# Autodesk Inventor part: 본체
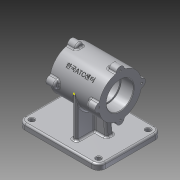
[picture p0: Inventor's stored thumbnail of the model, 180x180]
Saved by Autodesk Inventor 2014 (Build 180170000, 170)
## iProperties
Created: 2015-12
Part Number: 본체
Material: Aluminum 6061
Document SubType Name: Modeling
Designer: user
Density: 2.71 g/cm^3
Appearance: Aluminum - Flat
Author: user
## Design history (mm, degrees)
sketch "Sketch1"
  geometry: L1 (-42.5, 37)-(42.5, 37); L2 (42.5, 37)-(42.5, 0); L3 (42.5, 0)-(-42.5, 0); L4 (-42.5, 0)-(-42.5, 37); 2 further points
  constraints: 8 end point, 2 parallel, 1 coincident, 1 horizontal, 1 midpoint, 1 perpendicular
  dimensions: "d0" = 74 diameter of L1 L3; "d1" = 85 distance between parallel lines of L2 L4
revolve "Revolution1" sketch "Sketch1" stored, may be unused: angle "d2" = 90 deg
sketch "Sketch2"
  geometry: L1 (0, 1.084)-(0, 37); C1 r 7 at (0, 37); 2 further points
  constraints: 2 end point, 1 centre point, 1 coincident, 1 vertical, 1 vertical alignment, 1 other
  dimensions: "d3" = 14 diameter of C1
extrude "Extrusion1" join sketch "Sketch2" distance "d4" = 15; taper "d5" = 0 deg
mirror "Mirror1"
mirror "Mirror2"
sketch "Sketch5"
  geometry: L1 (-37, -37)-(37, -37); C1 r 7 at (-37, -37); A1 r 37 centre (0, -37) between (-6.969, -0.662) and (-6.969, -73.338) reference; A2 r 37 centre (0, -37) between (6.969, -73.338) and (6.969, -0.662) reference; 1 further point
  constraints: 2 end point, 2 point on circle, 1 centre point, 1 coincident
  dimensions: "d10" = 14 diameter of C1
extrude "Extrusion2" join sketch "Sketch5" distance "d11" = 15; taper "d12" = 0 deg
mirror "Mirror3"
mirror "Mirror4"
workplane "Work Plane16"
sketch "Sketch6"
  geometry: L1 (-80, 55)-(60, 55); L2 (60, 55)-(60, -55); L3 (60, -55)-(-80, -55); L4 (-80, -55)-(-80, 55); L5 (0, 0)-(0, -58.953); 1 further point
  constraints: 10 end point, 3 parallel, 1 horizontal, 1 horizontal alignment, 1 midpoint, 1 perpendicular
  dimensions: "d16" = 140 distance between parallel lines of L2 L4; "d17" = 110 distance between parallel lines of L3 L1
extrude "Extrusion3" join sketch "Sketch6" distance "d19" = 10; taper "d20" = 0 deg
sketch "Sketch7"
  geometry: L1 (0, 0)-(0, -86.371); L2 (-25, -70)-(-19.566, -25.742); L3 (-19.566, -25.742)-(19.566, -25.742); L4 (19.566, -25.742)-(25, -70); L5 (25, -70)-(-25, -70); L6 (80, -70)-(-60, -70) reference; 1 further point
  constraints: 10 end point, 1 equal length, 1 midpoint, 1 parallel, 1 perpendicular, 1 point on line, 1 vertical, 1 vertical alignment
  dimensions: "d22" = 97 deg angle of L5 L2; "d29" = 50 distance of L4.end L2.start
extrude "Extrusion4" join sketch "Sketch7" stored distance "d23" = 12; taper "d24" = 0 deg
sketch "Sketch8"
  geometry: L1 (-4, 37)-(4, 37); L2 (4, 37)-(4, -37); L3 (4, -37)-(-4, -37); L4 (-4, -37)-(-4, 37); L5 (-80, -55)-(-80, 55) reference; 3 further points
  constraints: 8 end point, 2 midpoint, 2 parallel, 1 horizontal, 1 horizontal alignment, 1 perpendicular, 1 vertical alignment
  dimensions: "d25" = 8 distance between parallel lines of L2 L4; "d26" = 74 distance between parallel lines of L3 L1
extrude "Extrusion5" join sketch "Sketch8" stored distance "d27" = 8; taper "d28" = 0 deg
sketch "Sketch9"
  geometry: L1 (-42.5, -36.338)-(-27.5, -36.338) reference; L2 (-27.5, -36.338)-(-27.5, -36.338) reference; L3 (-27.5, -36.338)-(-42.5, -36.338) reference; L4 (-42.5, -36.338)-(-42.5, -6.969) reference; L5 (-42.5, -6.969)-(-27.5, -6.969) reference; L6 (-27.5, -6.969)-(-27.5, 6.969) reference; L7 (-27.5, 6.969)-(-42.5, 6.969) reference; L8 (-42.5, 6.969)-(-42.5, 36.338) reference; L9 (-42.5, 36.338)-(-27.5, 36.338) reference; L10 (-27.5, 36.338)-(-27.5, 36.338) reference; L11 (-27.5, 36.338)-(-42.5, 36.338) reference; L12 (-42.5, 36.338)-(-42.5, 6.969) reference; L13 (-42.5, 6.969)-(-27.5, 6.969) reference; L14 (-27.5, 6.969)-(-27.5, -6.969) reference; L15 (-27.5, -6.969)-(-42.5, -6.969) reference; L16 (-42.5, -6.969)-(-42.5, -36.338) reference; L17 (27.5, -36.338)-(42.5, -36.338) reference; L18 (42.5, -6.969)-(42.5, -36.338) reference; L19 (42.5, -6.969)-(27.5, -6.969) reference; L20 (27.5, -6.969)-(27.5, 6.969) reference; L21 (27.5, 6.969)-(42.5, 6.969) reference; L22 (42.5, 36.338)-(42.5, 6.969) reference; L23 (42.5, 36.338)-(27.5, 36.338) reference; L24 (27.5, 36.338)-(27.5, 36.338) reference; L25 (27.5, 36.338)-(42.5, 36.338) reference; L26 (42.5, 6.969)-(42.5, 36.338) reference; L27 (42.5, 6.969)-(27.5, 6.969) reference; L28 (27.5, 6.969)-(27.5, -6.969) reference; L29 (27.5, -6.969)-(42.5, -6.969) reference; L30 (42.5, -36.338)-(42.5, -6.969) reference; L31 (42.5, -36.338)-(27.5, -36.338) reference; L32 (27.5, -36.338)-(27.5, -36.338) reference; L33 (-4, 0)-(4, 0) reference; L34 (-4, 0)-(-4, -36.51) reference; L35 (-4, -36.51)-(-20.888, -36.51) reference; L36 (-20.888, -36.51)-(-20.888, -36.51) reference; L37 (-20.888, -36.51)-(-4, -36.51) reference; L38 (-4, -36.51)-(-4, 0) reference; L39 (-4, 0)-(4, 0) reference; L40 (4, 0)-(4, -36.51) reference; L41 (4, -36.51)-(20.888, -36.51) reference; L42 (20.888, -36.51)-(20.888, -36.51) reference; L43 (20.888, -36.51)-(4, -36.51) reference; L44 (4, -36.51)-(4, 0) reference; L45 (-42.5, 23.5)-(-20.5, 23.5); L46 (-20.5, 23.5)-(-20.5, 21); L47 (-20.5, 21)-(20.5, 21); L48 (20.5, 21)-(20.5, 23.5); L49 (20.5, 23.5)-(42.5, 23.5); L50 (42.5, 0)-(-42.5, 0); L51 (-42.5, 23.5)-(-42.5, 0); L52 (42.5, 0)-(42.5, 23.5); 1 further point
  constraints: 16 end point, 3 collinear, 3 parallel, 3 point on line, 2 perpendicular
  dimensions: "d30" = 47 diameter of L45 L50; "d31" = 42 diameter of L47 L50; "d32" = 47 diameter of L49 L50; "d33" = 22 distance between parallel lines of L8 L46; "d34" = 41 distance between parallel lines of L48 L46
revolve "Revolution2" sketch "Sketch9" stored, may be unused: angle "d35" = 90 deg
sketch "Sketch10"
  geometry: A1 r 37 centre (0, -37) between (0, 0) and (-37, -37); 3 further points
  constraints: 4 point on circle, 1 centre point, 1 coincident
  dimensions: "d36" = 74 diameter of A1
hole "Hole1" sketch "Sketch10" at (0, 0), (-37, -37), (37, -37), (0, -74) diameter "d37" = 3.242; stored, may be unused: countersink angle "d41" = 90 deg, drill point angle "d43" = 120 deg; dims "d38" = 9, "d39" = 4, "d40" = 2, "d42" = 11
mirror "Mirror5"
sketch "Sketch11"
  geometry: L1 (-80, 55)-(60, 55) reference; L2 (60, 55)-(60, -55) reference; L3 (60, -55)-(-80, -55) reference; L4 (-80, -55)-(-80, 55) reference; L5 (48, 43)-(-68, 43); L6 (-68, 43)-(-68, -43); L7 (-68, -43)-(48, -43); L8 (48, -43)-(48, 43); C1 r 4 at (-68, 43); C2 r 4 at (-68, -43); C3 r 4 at (48, -43); C4 r 4 at (48, 43); 5 further points
  constraints: 8 coincident, 8 end point, 4 centre point, 3 equal radius, 3 other
  dimensions: "d45" = 12 distance between parallel lines of L6 L4; "d46" = 8 diameter of C1
  node "Projected Loop3"
sketch "Sketch12"
  geometry: 1 further point
extrude "Extrusion6" cut sketch "Sketch11" stored distance "d47" = 8; taper "d48" = 0 deg
fillet "Fillet1" dims "d49" = 12
fillet "Fillet2" dims "d50" = 3
fillet "Fillet3" dims "d51" = 3
fillet "Fillet4" dims "d52" = 3
fillet "Fillet5" dims "d53" = 3
fillet "Fillet6" dims "d54" = 3
chamfer "Chamfer1" distance "d55" = 1; stored, may be unused: second distance "d56" = 2, angle "d57" = 45 deg
fillet "Fillet7" dims "d58" = 0.3
fillet "Fillet8" dims "d59" = 3
sketch "Sketch14"
  geometry: 1 further point
workplane "Work Plane17"
sketch "Sketch15"
  geometry: 1 further point
sketch "Sketch16"
  geometry: 1 further point
sketch "Sketch17"
  geometry: 1 further point
sketch "Sketch18"
  geometry: L1 (0, 0)-(-27.551, 27.551); L2 (-0.03, 0.03)-(-29.041, 0.03); A1 r 37 centre (0, 0) between (-9.104, 35.863) and (-35.863, 9.104) reference; 2 further points
  constraints: 4 end point, 1 coincident, 1 horizontal, 1 point on circle, 1 point on line
  dimensions: "d61" = 45 deg angle of L2 L1
workplane "Work Plane18"
sketch "Sketch19"
  geometry: 2 further points
  constraints: 1 coincident, 1 other
emboss "Emboss1" sketch "Sketch19" dims "d62" = 0.5, "d63" = 0
chamfer "Chamfer2" distance "d64" = 1; stored, may be unused: second distance "d65" = 2, angle "d66" = 45 deg
body "Solid1"
workplane "Work Plane1"
workplane "Work Plane2"
workplane "Work Plane3"
node "Projected Loop2"
